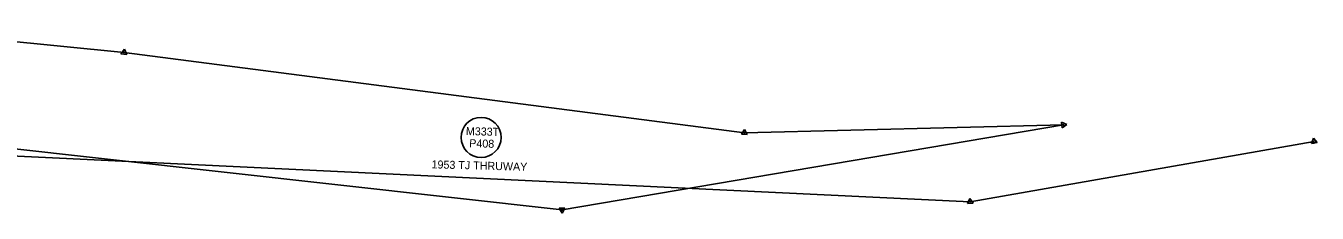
# Model space of a CAD drawing. Extents: x 325029 to 414988, y 1517527 to 1550420.
# Drawn here: x 364852 to 365699, y 1524431 to 1524554 of the extents above; entities that cross this region are included whole.
import ezdxf

# ---------------------------------------------------------------- set-up
doc = ezdxf.new("R2010")
doc.units = 0
for name, color, linetype in [('Level 56', 7, 'Continuous'), ('MHB', 7, 'Continuous'), ('MRBL1', 7, 'Continuous')]:
    doc.layers.add(name, color=color, linetype=linetype)

msp = doc.modelspace()

# ---------------------------------------------------------------- linework, layer by layer
at = {"layer": 'Level 56'}
msp.add_circle((365150.96, 1524480.6), 13.12, dxfattribs=at)
at = {"layer": 'MHB'}
for p, q in [((364741.34, 1524553.57), (364916.71, 1524536.17)), ((364916.71, 1524536.17), (365323.66, 1524483.66)), ((365532.92, 1524488.81), (365204.12, 1524433.31)), ((365323.66, 1524483.66), (365532.92, 1524488.81)), ((365204.12, 1524433.31), (364776.9, 1524480.78))]:
    msp.add_line(p, q, dxfattribs=at)
for points in [[(364914.7, 1524535.29), (364916.95, 1524538.33)], [(364916.95, 1524538.33), (364918.46, 1524534.86)], [(364918.46, 1524534.86), (364914.7, 1524535.29)], [(365531.65, 1524490.59), (365535.09, 1524489.02)], [(365532.02, 1524486.83), (365531.65, 1524490.59)], [(365535.09, 1524489.02), (365532.02, 1524486.83)], [(365321.72, 1524482.66), (365323.77, 1524485.83)], [(365325.49, 1524482.47), (365321.72, 1524482.66)], [(365323.77, 1524485.83), (365325.49, 1524482.47)], [(365202.2, 1524434.35), (365205.98, 1524434.46)], [(365204.18, 1524431.13), (365202.2, 1524434.35)], [(365205.98, 1524434.46), (365204.18, 1524431.13)]]:
    msp.add_lwpolyline(points, dxfattribs=at)
for centre in [(364916.71, 1524536.17), (365532.92, 1524488.81), (365323.66, 1524483.66), (365204.12, 1524433.31)]:
    msp.add_circle(centre, 0.227, dxfattribs=at)
at = {"layer": 'MRBL1'}
for p, q in [((364151.59, 1524501.69), (365471.78, 1524438.52)), ((365471.78, 1524438.52), (365697.35, 1524477.98))]:
    msp.add_line(p, q, dxfattribs=at)
for points in [[(365695.68, 1524476.58), (365696.97, 1524480.13)], [(365696.97, 1524480.13), (365699.4, 1524477.23)], [(365699.4, 1524477.23), (365695.68, 1524476.58)], [(365469.97, 1524437.31), (365471.65, 1524440.7)], [(365473.74, 1524437.55), (365469.97, 1524437.31)], [(365471.65, 1524440.7), (365473.74, 1524437.55)]]:
    msp.add_lwpolyline(points, dxfattribs=at)
for centre, radius in [((365697.35, 1524477.98), 1.09), ((365471.78, 1524438.52), 0.227)]:
    msp.add_circle(centre, radius, dxfattribs=at)

# ---------------------------------------------------------------- texts
at = {"layer": 'Level 56'}
for s, height, p in [('M333T', 5.249, (365140.92, 1524482.18)), ('P408', 5.249, (365143.12, 1524474.24)), ('1953 TJ THRUWAY', 5.2493, (365118.41, 1524460.43))]:
    msp.add_text(s, height=height, rotation=358.49067, dxfattribs=at).set_placement(p)

doc.saveas('drawing.dxf')
